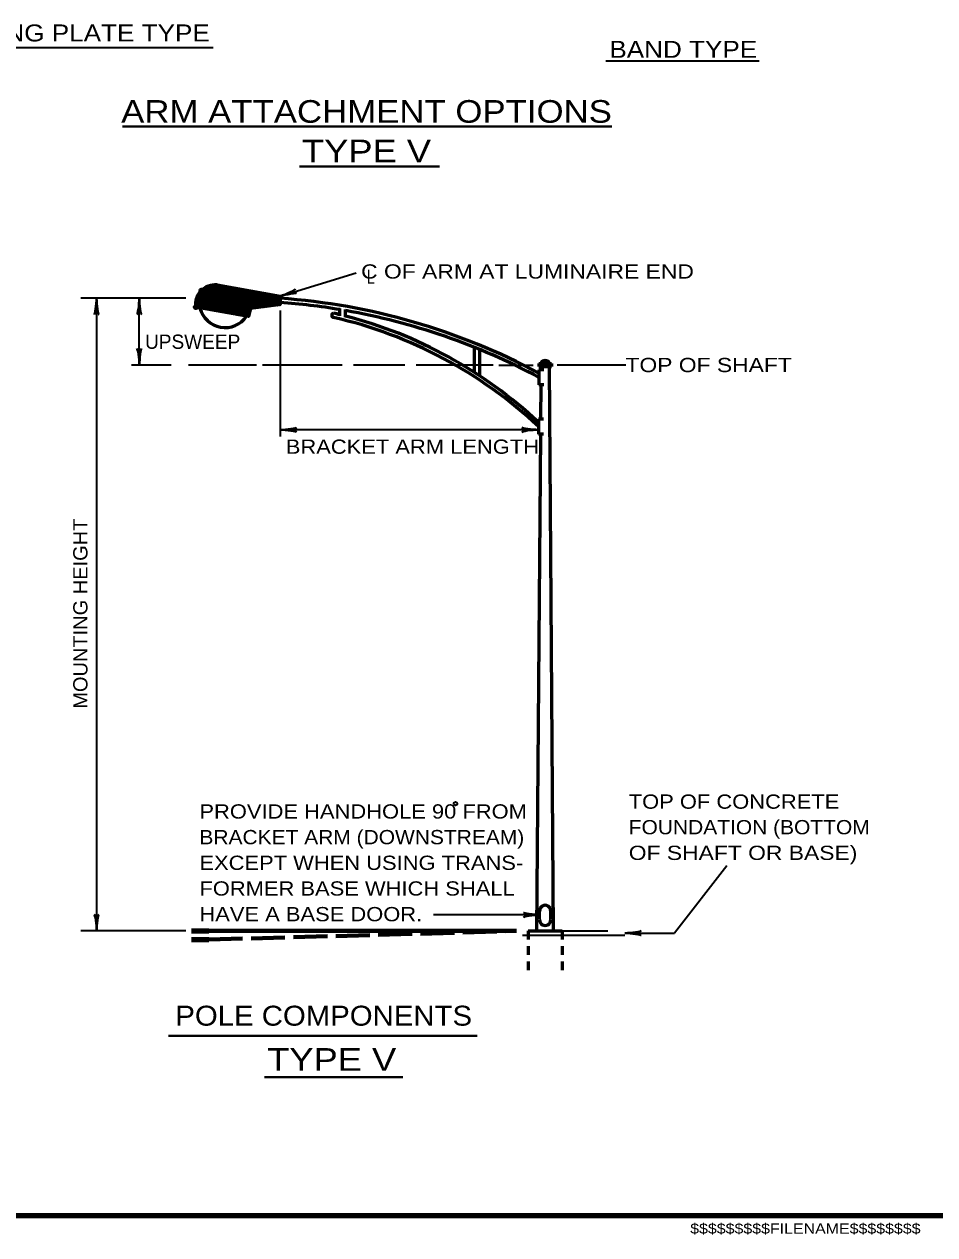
# Model space of a CAD drawing. Extents: x -20 to 693, y -19 to 435.
# Drawn here: x 342.4 to 503.5, y -12.4 to 201.6 of the extents above; entities that cross this region are included whole.
import ezdxf
from ezdxf.enums import TextEntityAlignment as Align

# ---------------------------------------------------------------- set-up
doc = ezdxf.new("R2010")
doc.units = 0
doc.header["$PDMODE"] = 32
doc.header["$PDSIZE"] = 0.5
doc.linetypes.add('LONG_DASHED', pattern=[7.5, 6, -1.5])
doc.linetypes.add('SHORT_DASHED', pattern=[2.7, 1.5, -1.2])
doc.layers.add('1', color=7, linetype='Continuous', lineweight=53)

msp = doc.modelspace()

# ---------------------------------------------------------------- linework, layer by layer
at = {"layer": '1', "lineweight": 35}
for p, q in [((319.818, 197.514), (375.824, 197.514)), ((445.285, 195.172), (472.428, 195.172)), ((387.694, 153.562), (401.114, 157.702)), ((371.014, 153.182), (352.414, 153.182)), ((355.214, 153.182), (355.214, 41.302)), ((362.774, 141.382), (362.774, 153.182)), ((387.694, 151.042), (387.694, 128.722)), ((368.414, 141.382), (361.374, 141.382)), ((383.534, 141.382), (371.454, 141.382)), ((398.654, 141.382), (384.554, 141.382)), ((409.754, 141.382), (400.674, 141.382)), ((425.374, 141.382), (411.774, 141.382)), ((426.374, 141.382), (432.434, 141.382)), ((448.814, 141.382), (436.714, 141.382)), ((433.374, 129.922), (387.694, 129.922)), ((466.734, 52.842), (457.474, 40.942)), ((433.634, 44.142), (414.794, 44.142)), ((371.014, 41.302), (352.414, 41.302)), ((437.594, 41.302), (445.654, 41.302)), ((448.674, 40.942), (457.474, 40.942)), ((430.534, 40.542), (448.674, 40.542))]:
    msp.add_line(p, q, dxfattribs=at)
at = {"layer": '1', "lineweight": 40}
for p, q in [((359.805, 183.548), (446.358, 183.548)), ((391.133, 176.46), (415.859, 176.46)), ((367.934, 22.742), (422.514, 22.742)), ((384.945, 15.463), (409.384, 15.463))]:
    msp.add_line(p, q, dxfattribs=at)
at = {"layer": '1'}
for p, q in [((372.814, 152.882), (375.414, 155.462)), ((372.854, 153.002), (375.274, 155.422)), ((372.914, 153.162), (375.114, 155.382)), ((372.954, 153.322), (374.954, 155.322)), ((373.034, 153.522), (374.774, 155.242)), ((373.134, 153.722), (374.554, 155.142)), ((373.294, 153.982), (374.294, 154.982)), ((373.334, 153.282), (375.554, 155.482)), ((373.454, 153.282), (375.674, 155.522)), ((373.554, 153.282), (375.794, 155.522)), ((373.654, 153.282), (375.914, 155.542)), ((373.774, 153.282), (376.034, 155.542)), ((373.874, 153.282), (376.134, 155.542)), ((373.974, 153.282), (376.254, 155.542)), ((374.094, 153.282), (376.354, 155.542)), ((374.194, 153.282), (376.454, 155.542)), ((374.294, 153.282), (376.554, 155.542)), ((374.414, 153.282), (376.634, 155.522)), ((374.514, 153.282), (376.734, 155.502)), ((374.614, 153.282), (376.814, 155.482)), ((374.734, 153.282), (376.914, 155.462)), ((374.834, 153.282), (377.014, 155.462)), ((374.934, 153.282), (377.094, 155.442)), ((375.054, 153.282), (377.194, 155.422)), ((375.154, 153.282), (377.274, 155.402)), ((375.254, 153.282), (377.374, 155.382)), ((375.374, 153.282), (377.454, 155.382)), ((375.474, 153.282), (377.554, 155.362)), ((375.594, 153.282), (377.634, 155.342)), ((375.694, 153.282), (377.734, 155.322)), ((375.794, 153.282), (377.814, 155.302)), ((375.914, 153.282), (377.914, 155.302)), ((376.014, 153.282), (378.014, 155.282)), ((376.114, 153.282), (378.094, 155.262)), ((376.234, 153.282), (378.194, 155.242)), ((376.334, 153.282), (378.274, 155.222)), ((376.434, 153.282), (378.374, 155.222)), ((376.554, 153.282), (378.454, 155.202)), ((376.654, 153.282), (378.554, 155.182)), ((376.754, 153.282), (378.634, 155.162)), ((376.874, 153.282), (378.734, 155.142)), ((376.974, 153.282), (378.814, 155.122)), ((377.074, 153.282), (378.914, 155.122)), ((377.194, 153.282), (379.014, 155.102)), ((377.294, 153.282), (379.094, 155.082)), ((377.394, 153.282), (379.194, 155.062)), ((377.514, 153.282), (379.274, 155.042)), ((377.614, 153.282), (379.374, 155.042)), ((377.714, 153.282), (379.454, 155.022)), ((377.834, 153.282), (379.554, 155.002)), ((377.934, 153.282), (379.634, 154.982)), ((378.034, 153.282), (379.734, 154.962)), ((378.154, 153.282), (379.814, 154.962)), ((378.254, 153.282), (379.914, 154.942)), ((378.374, 153.282), (380.014, 154.922)), ((378.474, 153.282), (380.094, 154.902)), ((378.574, 153.282), (380.194, 154.882)), ((378.694, 153.282), (380.274, 154.882)), ((378.794, 153.282), (380.374, 154.862)), ((378.894, 153.282), (380.454, 154.842)), ((379.014, 153.282), (380.554, 154.822)), ((379.114, 153.282), (380.634, 154.802)), ((379.214, 153.282), (380.734, 154.802)), ((379.334, 153.282), (380.814, 154.782)), ((379.434, 153.282), (380.914, 154.762)), ((379.534, 153.282), (381.014, 154.742)), ((379.654, 153.282), (381.094, 154.722)), ((379.754, 153.282), (381.194, 154.722)), ((379.854, 153.282), (381.274, 154.702)), ((379.974, 153.282), (381.374, 154.682)), ((380.074, 153.282), (381.454, 154.662)), ((380.174, 153.282), (381.554, 154.642)), ((380.294, 153.282), (381.634, 154.642)), ((380.394, 153.282), (381.734, 154.622)), ((380.494, 153.282), (381.814, 154.602)), ((380.614, 153.282), (381.914, 154.582)), ((380.714, 153.282), (382.014, 154.562)), ((380.814, 153.282), (382.094, 154.562)), ((380.934, 153.282), (382.194, 154.542)), ((381.034, 153.282), (382.274, 154.522)), ((381.134, 153.282), (382.374, 154.502)), ((381.254, 153.282), (382.454, 154.482)), ((381.354, 153.282), (382.554, 154.482)), ((381.474, 153.282), (382.634, 154.462)), ((381.574, 153.282), (382.734, 154.442)), ((381.674, 153.282), (382.814, 154.422)), ((381.794, 153.282), (382.914, 154.402)), ((381.894, 153.282), (382.994, 154.402)), ((381.994, 153.282), (383.094, 154.382)), ((382.114, 153.282), (383.194, 154.362)), ((382.214, 153.282), (383.274, 154.342)), ((382.314, 153.282), (383.374, 154.322)), ((382.434, 153.282), (383.454, 154.322)), ((382.534, 153.282), (383.554, 154.302)), ((382.634, 153.282), (383.634, 154.282)), ((382.754, 153.282), (383.734, 154.262)), ((382.854, 153.282), (383.814, 154.242)), ((382.954, 153.282), (383.914, 154.242)), ((383.074, 153.282), (383.994, 154.222)), ((383.174, 153.282), (384.094, 154.202)), ((383.274, 153.282), (384.194, 154.182)), ((383.394, 153.282), (384.274, 154.162)), ((383.494, 153.282), (384.374, 154.162)), ((383.594, 153.282), (384.454, 154.142)), ((383.714, 153.282), (384.554, 154.122)), ((372.734, 152.362), (373.474, 153.102)), ((372.734, 152.242), (373.574, 153.102)), ((372.734, 152.142), (373.694, 153.102)), ((372.734, 152.042), (373.794, 153.102)), ((372.734, 151.922), (373.894, 153.102)), ((372.734, 151.842), (374.014, 153.102)), ((372.754, 152.482), (373.354, 153.102)), ((372.754, 151.742), (374.114, 153.102)), ((372.754, 151.642), (374.214, 153.102)), ((372.774, 152.602), (373.314, 153.162)), ((372.794, 152.742), (373.314, 153.262)), ((372.814, 151.582), (374.334, 153.102)), ((372.914, 151.562), (374.434, 153.102)), ((372.994, 151.562), (374.534, 153.102)), ((373.094, 151.542), (374.654, 153.102)), ((373.174, 151.522), (374.754, 153.102)), ((373.274, 151.502), (374.854, 153.102)), ((373.354, 151.482), (374.974, 153.102)), ((373.454, 151.482), (375.074, 153.102)), ((373.554, 151.462), (375.174, 153.102)), ((373.634, 151.442), (375.294, 153.102)), ((373.734, 151.422), (375.394, 153.102)), ((373.814, 151.402), (375.494, 153.102)), ((373.914, 151.402), (375.614, 153.102)), ((373.994, 151.382), (375.714, 153.102)), ((374.094, 151.362), (375.814, 153.102)), ((374.174, 151.342), (375.934, 153.102)), ((374.274, 151.322), (376.034, 153.102)), ((374.354, 151.322), (376.134, 153.102)), ((374.454, 151.302), (376.254, 153.102)), ((374.534, 151.282), (376.354, 153.102)), ((374.634, 151.262), (376.474, 153.102)), ((374.734, 151.242), (376.574, 153.102)), ((374.814, 151.242), (376.674, 153.102)), ((374.914, 151.222), (376.794, 153.102)), ((374.994, 151.202), (376.894, 153.102)), ((375.094, 151.182), (376.994, 153.102)), ((375.174, 151.162), (377.114, 153.102)), ((375.274, 151.162), (377.214, 153.102)), ((375.354, 151.142), (377.314, 153.102)), ((375.454, 151.122), (377.434, 153.102)), ((375.534, 151.102), (377.534, 153.102)), ((375.634, 151.082), (377.634, 153.102)), ((375.734, 151.082), (377.754, 153.102)), ((375.814, 151.062), (377.854, 153.102)), ((375.914, 151.042), (377.954, 153.102)), ((375.994, 151.022), (378.074, 153.102)), ((376.094, 151.002), (378.174, 153.102)), ((376.174, 151.002), (378.274, 153.102)), ((376.274, 150.982), (378.394, 153.102)), ((376.354, 150.962), (378.494, 153.102)), ((376.454, 150.942), (378.594, 153.102)), ((376.534, 150.922), (378.714, 153.102)), ((376.634, 150.902), (378.814, 153.102)), ((376.734, 150.902), (378.914, 153.102)), ((376.814, 150.882), (379.034, 153.102)), ((376.914, 150.862), (379.134, 153.102)), ((376.994, 150.842), (379.254, 153.102)), ((377.094, 150.822), (379.354, 153.102)), ((377.174, 150.822), (379.454, 153.102)), ((377.274, 150.802), (379.574, 153.102)), ((377.354, 150.782), (379.674, 153.102)), ((377.454, 150.762), (379.774, 153.102)), ((377.534, 150.742), (379.894, 153.102)), ((377.634, 150.742), (379.994, 153.102)), ((377.734, 150.722), (380.094, 153.102)), ((377.814, 150.702), (380.214, 153.102)), ((377.914, 150.682), (380.314, 153.102)), ((377.994, 150.662), (380.414, 153.102)), ((378.094, 150.662), (380.534, 153.102)), ((378.174, 150.642), (380.634, 153.102)), ((378.274, 150.622), (380.734, 153.102)), ((378.354, 150.602), (380.854, 153.102)), ((378.454, 150.582), (380.954, 153.102)), ((378.534, 150.582), (381.054, 153.102)), ((378.634, 150.562), (381.174, 153.102)), ((378.734, 150.542), (381.274, 153.102)), ((378.814, 150.522), (381.374, 153.102)), ((378.914, 150.502), (381.494, 153.102)), ((378.994, 150.502), (381.594, 153.102)), ((379.094, 150.482), (381.694, 153.102)), ((379.174, 150.462), (381.814, 153.102)), ((379.274, 150.442), (381.914, 153.102)), ((379.354, 150.422), (382.034, 153.102)), ((379.454, 150.422), (382.134, 153.102)), ((379.534, 150.402), (382.234, 153.102)), ((379.634, 150.382), (382.354, 153.102)), ((379.734, 150.362), (382.454, 153.102)), ((379.814, 150.342), (382.554, 153.102)), ((379.914, 150.342), (382.674, 153.102)), ((379.994, 150.322), (382.774, 153.102)), ((380.094, 150.302), (382.874, 153.102)), ((380.174, 150.282), (382.994, 153.102)), ((380.274, 150.262), (383.094, 153.102)), ((380.354, 150.262), (383.194, 153.102)), ((380.454, 150.242), (383.314, 153.102)), ((380.534, 150.222), (383.414, 153.102)), ((380.634, 150.202), (383.514, 153.102)), ((380.734, 150.182), (383.634, 153.102)), ((380.814, 150.182), (383.734, 153.102)), ((380.914, 150.162), (383.834, 153.102)), ((380.994, 150.142), (383.954, 153.102)), ((381.094, 150.122), (384.054, 153.102)), ((382.474, 151.422), (384.154, 153.102)), ((382.614, 151.422), (384.274, 153.102)), ((382.734, 151.442), (384.374, 153.102)), ((382.854, 151.462), (384.474, 153.102)), ((382.974, 151.482), (384.594, 153.102)), ((383.094, 151.482), (384.694, 153.102)), ((383.214, 151.502), (384.794, 153.102)), ((383.334, 151.522), (384.914, 153.102)), ((383.454, 151.542), (385.014, 153.102)), ((383.574, 151.542), (385.134, 153.102)), ((383.694, 151.562), (385.234, 153.102)), ((383.814, 153.282), (384.634, 154.102)), ((383.814, 151.582), (385.334, 153.102)), ((383.914, 153.282), (384.734, 154.082)), ((383.954, 151.602), (385.454, 153.102)), ((384.034, 153.282), (384.814, 154.082)), ((384.074, 151.602), (385.554, 153.102)), ((384.134, 153.282), (384.914, 154.062)), ((384.194, 151.622), (385.654, 153.102)), ((384.254, 153.282), (384.994, 154.042)), ((384.314, 151.642), (385.774, 153.102)), ((384.354, 153.282), (385.094, 154.022)), ((384.434, 151.662), (385.874, 153.102)), ((384.454, 153.282), (385.194, 154.002)), ((384.554, 151.662), (385.974, 153.102)), ((384.574, 153.282), (385.274, 154.002)), ((384.674, 153.282), (385.374, 153.982)), ((384.674, 151.682), (386.094, 153.102)), ((384.774, 153.282), (385.454, 153.962)), ((384.794, 151.702), (386.194, 153.102)), ((384.894, 153.282), (385.554, 153.942)), ((384.914, 151.722), (386.294, 153.102)), ((384.994, 153.282), (385.634, 153.922)), ((385.034, 151.722), (386.414, 153.102)), ((385.094, 153.282), (385.734, 153.922)), ((385.154, 151.742), (386.514, 153.102)), ((385.214, 153.282), (385.814, 153.902)), ((385.294, 151.762), (386.614, 153.102)), ((385.314, 153.282), (385.914, 153.882)), ((385.414, 153.282), (385.994, 153.862)), ((385.414, 151.782), (386.734, 153.102)), ((385.534, 153.282), (386.094, 153.842)), ((385.534, 151.782), (386.834, 153.102)), ((385.634, 153.282), (386.194, 153.842)), ((385.654, 151.802), (386.934, 153.102)), ((385.734, 153.282), (386.274, 153.822)), ((385.774, 151.822), (387.054, 153.102)), ((385.854, 153.282), (386.374, 153.802)), ((385.894, 151.842), (387.154, 153.102)), ((385.954, 153.282), (386.454, 153.782)), ((386.014, 151.842), (387.254, 153.102)), ((386.054, 153.282), (386.554, 153.762)), ((386.134, 151.862), (387.694, 153.422)), ((386.174, 153.282), (386.634, 153.762)), ((386.254, 151.882), (387.694, 153.322)), ((386.274, 153.282), (386.734, 153.742)), ((386.374, 153.282), (386.814, 153.722)), ((386.374, 151.902), (387.694, 153.202)), ((386.494, 153.282), (386.914, 153.702)), ((386.514, 151.902), (387.694, 153.102)), ((386.594, 153.282), (386.994, 153.682)), ((386.634, 151.922), (387.694, 153.002)), ((386.694, 153.282), (387.094, 153.682)), ((386.754, 151.942), (387.694, 152.882)), ((386.814, 153.282), (387.194, 153.662)), ((386.874, 151.962), (387.694, 152.782)), ((386.914, 153.282), (387.274, 153.642)), ((386.994, 151.962), (387.694, 152.682)), ((387.034, 153.282), (387.374, 153.622)), ((387.114, 151.982), (387.694, 152.562)), ((387.134, 153.282), (387.454, 153.602)), ((387.234, 153.282), (387.554, 153.602)), ((387.234, 152.002), (387.694, 152.462)), ((387.314, 153.262), (387.634, 153.582)), ((387.314, 153.162), (387.694, 153.522)), ((387.354, 152.022), (387.694, 152.362)), ((387.474, 152.022), (387.694, 152.242)), ((387.594, 152.042), (387.694, 152.142)), ((381.174, 150.102), (382.434, 151.362)), ((381.274, 150.102), (382.414, 151.222)), ((381.354, 150.082), (382.374, 151.082)), ((381.454, 150.062), (382.334, 150.962)), ((381.534, 150.042), (382.314, 150.822)), ((381.634, 150.022), (382.274, 150.682)), ((381.714, 150.022), (382.254, 150.542)), ((381.814, 150.002), (382.214, 150.402)), ((381.914, 149.982), (382.174, 150.262)), ((381.994, 149.962), (382.154, 150.122)), ((382.094, 149.942), (382.114, 149.982)), ((398.274, 150.082), (398.274, 151.362)), ((399.234, 149.842), (399.234, 151.202)), ((422.094, 140.042), (422.094, 144.502)), ((423.034, 139.442), (423.034, 144.102)), ((433.434, 141.662), (435.714, 141.662)), ((433.434, 141.662), (433.434, 141.102)), ((435.714, 141.662), (435.714, 141.102)), ((433.434, 141.102), (435.714, 141.102)), ((434.314, 140.522), (433.434, 140.522)), ((433.434, 140.522), (433.434, 137.882)), ((433.814, 141.102), (433.814, 140.522)), ((436.074, 41.302), (435.334, 141.102)), ((434.314, 137.882), (433.434, 137.882)), ((433.794, 137.882), (433.754, 131.822)), ((434.254, 131.822), (433.374, 131.822)), ((433.374, 131.822), (433.374, 129.182)), ((433.734, 129.182), (433.054, 41.302)), ((434.254, 129.182), (433.374, 129.182)), ((433.574, 43.322), (433.574, 44.822)), ((435.574, 43.322), (435.574, 44.822)), ((431.554, 41.302), (437.594, 41.302))]:
    msp.add_line(p, q, dxfattribs=at)
at = {"layer": '1', "lineweight": 106}
for p, q in [((372.014, 41.302), (375.054, 41.302)), ((372.014, 39.782), (375.054, 39.782))]:
    msp.add_line(p, q, dxfattribs=at)
at = {"layer": '1', "lineweight": 70}
msp.add_line((375.054, 41.302), (429.474, 41.302), dxfattribs=at)
at = {"layer": '1', "linetype": 'LONG_DASHED', "lineweight": 70}
msp.add_line((375.054, 39.782), (429.474, 41.302), dxfattribs=at)
at = {"layer": '1', "linetype": 'SHORT_DASHED'}
for p, q in [((431.554, 41.302), (431.554, 33.242)), ((437.594, 41.302), (437.594, 33.242))]:
    msp.add_line(p, q, dxfattribs=at)
at = {"layer": '1', "lineweight": 158}
msp.add_line((687.723, -9.063), (28.056, -9.063), dxfattribs=at)
at = {"layer": '1'}
msp.add_lwpolyline([(376.534, 155.542), (387.694, 153.562), (387.694, 152.062), (382.454, 151.402), (382.114, 149.942), (372.774, 151.602)], dxfattribs=at)
msp.add_lwpolyline([(373.314, 153.282), (387.314, 153.282), (387.314, 153.102), (373.314, 153.102)], close=True, dxfattribs=at)
at = {"layer": '1', "lineweight": 35}
msp.add_circle((418.727, 63.819), 0.325, dxfattribs=at)
at = {"layer": '1'}
for centre, radius, start, end in [((376.185, 152.098), 3.456, 84.23953, 188.38162), ((379.504, 39.194), 114.289, 61.84402, 85.88743), ((379.504, 38.438), 114.289, 80.54208, 85.88743), ((377.946, 152.564), 4.57, 193.94762, 326.05059), ((397.212, 150.165), 0.383, 99.37484, 260.62516), ((397.325, 150.414), 0.651, 235.53017, 254.38288), ((379.623, 73.954), 78.568, 76.2603, 77.11012), ((379.504, 38.438), 114.289, 61.84402, 80.06146), ((379.623, 73.954), 78.568, 46.83897, 75.54976), ((379.623, 73.198), 78.568, 46.83897, 77.11012), ((434.572, 141.38), 0.802, 20.3922, 159.6078), ((434.572, 44.849), 0.993, 358.58875, 181.41125), ((434.572, 43.276), 0.993, 178.58875, 1.41125)]:
    msp.add_arc(centre, radius, start, end, dxfattribs=at)
at = {"layer": '1', "lineweight": 40}
for centre, major_axis, ratio, start_param, end_param in [((388.669, 154.156), (-1.674, -0.68), 0.122415, 0.8963533, 3.1415927), ((355.01, 152.059), (0.177, 1.77), 0.07063, 3.1407148, 5.41811), ((355.502, 152.089), (-0.157, 1.8), 0.122415, 0.8963533, 3.1415927), ((362.57, 152.059), (0.177, 1.77), 0.07063, 3.1407148, 5.41811), ((363.062, 152.089), (-0.157, 1.8), 0.122415, 0.8963533, 3.1415927), ((388.842, 153.695), (1.744, 0.352), 0.07063, 6.2823074, 8.5597026), ((362.505, 142.476), (0.157, -1.8), 0.122415, 0.8963533, 3.1415927), ((362.997, 142.506), (-0.177, -1.77), 0.07063, 3.1407148, 5.41811), ((388.829, 129.713), (-1.77, 0.177), 0.07063, 3.1407148, 5.41811), ((388.829, 129.713), (-1.77, 0.177), 0.07063, 3.1407148, 5.41811), ((388.8, 130.204), (-1.8, -0.157), 0.122415, 0.8963533, 3.1415927), ((388.8, 130.204), (-1.8, -0.157), 0.122415, 0.8963533, 3.1415927), ((432.268, 129.647), (1.8, 0.157), 0.122415, 0.8963533, 3.1415927), ((432.268, 129.647), (1.8, 0.157), 0.122415, 0.8963533, 3.1415927), ((432.238, 130.139), (1.77, -0.177), 0.07063, 3.1407148, 5.41811), ((432.238, 130.139), (1.77, -0.177), 0.07063, 3.1407148, 5.41811), ((354.945, 42.401), (0.157, -1.8), 0.122415, 0.8963533, 3.1415927), ((355.437, 42.43), (-0.177, -1.77), 0.07063, 3.1407148, 5.41811), ((432.542, 43.866), (1.8, 0.157), 0.122415, 0.8963533, 3.1415927), ((432.512, 44.358), (1.77, -0.177), 0.07063, 3.1407148, 5.41811), ((449.809, 40.724), (-1.77, 0.177), 0.07063, 3.1407148, 5.41811), ((449.78, 41.216), (-1.8, -0.157), 0.122415, 0.8963533, 3.1415927)]:
    msp.add_ellipse(centre, major_axis=major_axis, ratio=ratio, start_param=start_param, end_param=end_param, dxfattribs=at)
at = {"layer": '1'}
for p in [(373.774, 154.562), (372.774, 151.602)]:
    msp.add_point(p, dxfattribs=at)

# ---------------------------------------------------------------- texts
for s, height, width, p in [('MOUNTING PLATE TYPE', 3, 1.15, (320.902, 198.598)), ('BAND TYPE', 3, 1.15, (445.928, 195.698)), ('C OF ARM AT LUMINAIRE END', 2.52, 1.2, (402.014, 156.662)), ('L', 2.52, 0.75, (403.034, 155.742)), ('TOP OF SHAFT', 2.52, 1.2, (448.774, 140.122)), ('BRACKET ARM LENGTH', 2.52, 1.15, (388.694, 125.682)), ('TOP OF CONCRETE', 2.52, 1.15, (449.354, 62.922)), ('PROVIDE HANDHOLE 90 FROM', 2.52, 1.15, (373.414, 61.182)), ('FOUNDATION (BOTTOM', 2.52, 1.1, (449.354, 58.402)), ('BRACKET ARM (DOWNSTREAM)', 2.52, 1.1, (373.414, 56.642)), ('OF SHAFT OR BASE)', 2.52, 1.2, (449.354, 53.862)), ('EXCEPT WHEN USING TRANS-', 2.52, 1.15, (373.414, 52.102)), ('FORMER BASE WHICH SHALL', 2.52, 1.15, (373.414, 47.562)), ('HAVE A BASE DOOR.', 2.52, 1.15, (373.414, 43.022)), ('POLE COMPONENTS', 3.528, 1.1, (369.154, 24.562)), ('$$$$$$$$$FILENAME$$$$$$$$', 1.833, 1.15, (460.223, -12.23))]:
    msp.add_text(s, height=height, dxfattribs=dict(at, width=width)).set_placement(p)
for s, width, p in [('ARM ATTACHMENT OPTIONS', 1.15, (402.97, 184.221)), ('TYPE V', 1.2, (402.97, 177.221)), ('TYPE V', 1.2, (396.813, 16.592))]:
    msp.add_text(s, height=4, dxfattribs=dict(at, width=width)).set_placement(p, align=Align.CENTER)
msp.add_text('UPSWEEP', height=2.52, dxfattribs=at).set_placement((363.794, 144.242))
at = {"layer": '1', "width": 1.05}
msp.add_text('MOUNTING HEIGHT', height=2.52, rotation=90, dxfattribs=at).set_placement((353.614, 80.602))

doc.saveas('drawing.dxf')
